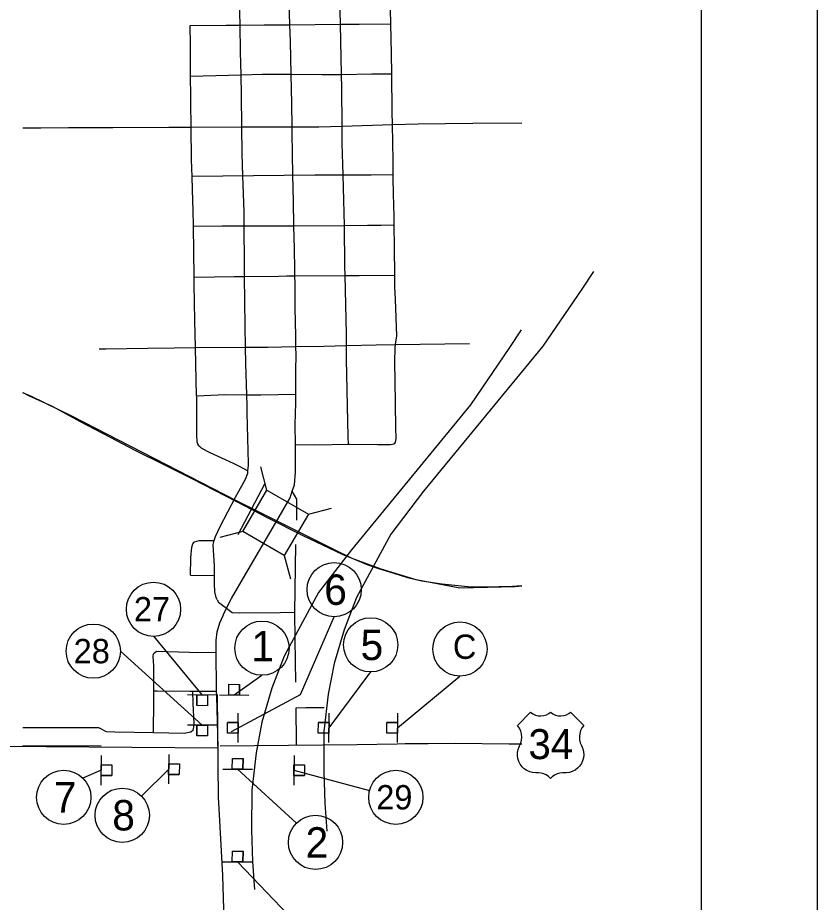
# Model space of a CAD drawing. Extents: x 10133 to 81668, y 5524 to 11018.
# Drawn here: x 16268 to 16868, y 8607 to 9270 of the extents above; entities that cross this region are included whole.
import ezdxf

# ---------------------------------------------------------------- set-up
doc = ezdxf.new("R2010")
doc.units = 0
for name, color, linetype in [('Default', 7, 'Continuous'), ('DisBoundDim', 7, 'Continuous'), ('DisCLMLOR', 7, 'Continuous'), ('DisCLMLSUR', 7, 'Continuous'), ('dsnShtPlotShapeBatchPrint', 7, 'Continuous'), ('Level 3', 7, 'Continuous'), ('trf_Signal_(Temp)_Layout', 7, 'Continuous'), ('trf_SignNumber_Text', 7, 'Continuous')]:
    doc.layers.add(name, color=color, linetype=linetype)

msp = doc.modelspace()

# ---------------------------------------------------------------- linework, layer by layer
at = {"layer": 'Default'}
for p, q in [((16454.98, 8916.03), (16450.39, 8933.39)), ((16433.27, 8882.64), (16453.27, 8920.74)), ((16486.01, 8897.96), (16503.37, 8902.55)), ((16436.91, 8884.99), (16419.55, 8880.41)), ((16467.95, 8866.93), (16472.53, 8849.57))]:
    msp.add_line(p, q, dxfattribs=at)
for points in [[(16434.84, 9264.84), (16434.67, 9274.29), (16433.96, 9308.38), (16433.89, 9316.19)], [(16510.01, 9265.38), (16509.79, 9275.33), (16509.65, 9309.42), (16509.32, 9316.37)], [(16547.84, 9265.77), (16547.84, 9265.77), (16547.29, 9287.29), (16546.86, 9304), (16546.66, 9316.69)], [(16418.34, 8723.02), (16417.4, 8761.37), (16417.24, 8765.29), (16417.16, 8771.93), (16416.96, 8789.48), (16416.96, 8794.43), (16416.96, 8803.2), (16417.67, 8809.71), (16419.65, 8816.36), (16422.05, 8822.05), (16422.33, 8822.73), (16424.76, 8827.47), (16428.42, 8834.61), (16439.17, 8853.28), (16461.38, 8891.34), (16472.41, 8910.29), (16473.97, 8915.18), (16475.53, 8920.06), (16476.38, 8929.39), (16476.29, 8950.19), (16476.23, 8965.33), (16476.52, 8981.31), (16476.57, 8988.1), (16476.71, 9006.22), (16476.8, 9016.96), (16476.58, 9023.71), (16476.5, 9031.84), (16476.09, 9052.47), (16476.09, 9071), (16475.97, 9076.7), (16475.87, 9081.59), (16475.56, 9096.87), (16475.2, 9114.2), (16474.82, 9132.4), (16474.49, 9152.29), (16473.97, 9184.18), (16473.88, 9188.52), (16473.52, 9205.7), (16473.06, 9227.89), (16472.56, 9252.37), (16472.21, 9265.05), (16471, 9308.81)], [(16397.53, 9264.43), (16424.35, 9264.8), (16434.84, 9264.84)], [(16397.77, 9226.48), (16397.71, 9244.04), (16397.69, 9250.03), (16397.53, 9264.43)], [(16434.84, 9264.84), (16452.96, 9264.91), (16459.44, 9264.94), (16472.18, 9265.05), (16510.01, 9265.38)], [(16435.53, 9227.56), (16435.21, 9244.76), (16434.84, 9264.84)], [(16510.01, 9265.38), (16524.09, 9265.5), (16547.84, 9265.77)], [(16510.83, 9227.86), (16510.01, 9265.38)], [(16548.56, 9228.21), (16548.41, 9243.59), (16547.84, 9265.77)], [(16397.77, 9226.48), (16435.53, 9227.56)], [(16399.85, 9113.98), (16399.85, 9113.98), (16399.67, 9126.1), (16399.45, 9132.64), (16398.83, 9151), (16398.83, 9151), (16398.39, 9164.02), (16398.1, 9188.23), (16397.88, 9206.75), (16397.83, 9211.41), (16397.77, 9226.48)], [(16435.53, 9227.56), (16451.51, 9228.01), (16473.04, 9227.89), (16496.12, 9227.76), (16500.46, 9227.73), (16510.83, 9227.86)], [(16437.86, 9114.22), (16437.78, 9124.76), (16437.56, 9131.59), (16436.9, 9151.86), (16436.37, 9168.19), (16436.11, 9188.37), (16435.8, 9212.33), (16435.53, 9227.56)], [(16510.83, 9227.86), (16533.57, 9228.16), (16548.56, 9228.21)], [(16512.12, 9152.47), (16511.48, 9175.88), (16511.35, 9189.08), (16511.06, 9217.47), (16510.83, 9227.86)], [(16549.69, 9152.66), (16549.54, 9163.24), (16549.02, 9190.16), (16548.84, 9199.45), (16548.56, 9228.21)], [(16271.9, 9187.81), (16285.4, 9187.84), (16306.1, 9187.88), (16309.31, 9187.89), (16325.09, 9187.95), (16339.51, 9188), (16381.5, 9188.16), (16398.1, 9188.23), (16436.11, 9188.37), (16473.86, 9188.51), (16493.97, 9188.59), (16511.35, 9189.08), (16549.02, 9190.16), (16568.24, 9190.71), (16609.38, 9191.12), (16646.09, 9191.48)], [(16399.03, 9151.43), (16490.98, 9152.47), (16512.12, 9152.47)], [(16512.12, 9152.47), (16533.14, 9152.47), (16549.69, 9152.66)], [(16513.03, 9114.48), (16512.9, 9124.1), (16512.12, 9152.47)], [(16550.33, 9114.9), (16550.25, 9118.67), (16549.97, 9132.4), (16549.92, 9135.59), (16549.69, 9152.66)], [(16399.85, 9113.98), (16421.38, 9114.27), (16437.86, 9114.22)], [(16400.43, 9075.72), (16399.85, 9113.98)], [(16437.86, 9114.22), (16455.17, 9114.17), (16467.22, 9114.13), (16475.17, 9114.19), (16513.03, 9114.48)], [(16438.18, 9076.3), (16438.07, 9085.57), (16437.86, 9114.22)], [(16513.03, 9114.48), (16530.33, 9114.62), (16540.64, 9114.7), (16550.33, 9114.9)], [(16513.61, 9076.98), (16513.47, 9083.64), (16513.03, 9114.48)], [(16550.88, 9077.26), (16550.68, 9098.02), (16550.33, 9114.9)], [(16400.43, 9075.72), (16430.43, 9076.22), (16438.18, 9076.3)], [(16438.18, 9076.3), (16463.66, 9076.58), (16469.9, 9076.64), (16475.95, 9076.69), (16476.01, 9076.69), (16513.61, 9076.98)], [(16438.95, 9023.22), (16438.63, 9039.31), (16438.18, 9076.3)], [(16699.75, 9080.1), (16690.96, 9066.76), (16661.71, 9023.97), (16572.44, 8915.18), (16547.74, 8883.05), (16522.03, 8835.36), (16512.85, 8811.29), (16505.34, 8785.98), (16500.94, 8762.86), (16497.64, 8734.98), (16497.55, 8705.05), (16498.28, 8681.21), (16499.87, 8660.29)], [(16513.61, 9076.98), (16524.09, 9077.07), (16550.88, 9077.26)], [(16516.11, 8950.45), (16515.73, 8955.89), (16514.6, 9014.32), (16514.6, 9024.42), (16514.6, 9033.13), (16513.61, 9076.98)], [(16516.11, 8950.45), (16516.86, 8950.47), (16537.8, 8950.19), (16547.71, 8950.19), (16550.11, 8950.61), (16550.11, 8950.61), (16550.76, 8951.34), (16551.24, 8951.88), (16551.81, 8954.57), (16551.67, 8962.92), (16551.05, 8998.18), (16550.82, 9011.87), (16551.1, 9023.04), (16551.37, 9025.11), (16552.23, 9031.67), (16551.29, 9059.06), (16550.96, 9068.6), (16550.88, 9077.26)], [(16401.35, 9022.91), (16400.94, 9043.2), (16400.51, 9070.22), (16400.43, 9075.72)], [(16645.64, 9036.2), (16636.85, 9022.87), (16607.59, 8980.08), (16518.32, 8871.29), (16493.62, 8839.16), (16467.91, 8791.47), (16458.74, 8767.39), (16451.22, 8742.08), (16446.82, 8718.97), (16443.52, 8691.09), (16443.43, 8661.16), (16444.16, 8637.31), (16445.75, 8616.39)], [(16438.95, 9023.22), (16455.53, 9023.35), (16476.55, 9023.7), (16476.64, 9023.71)], [(16476.64, 9023.71), (16497.69, 9024.06), (16514.6, 9024.42), (16536.88, 9024.91), (16551.37, 9025.11), (16606.9, 9025.9)], [(16329.24, 9021.94), (16334.15, 9021.94), (16365.52, 9022.46)], [(16365.52, 9022.46), (16385.5, 9022.79), (16401.35, 9022.91)], [(16401.35, 9022.91), (16438.95, 9023.22)], [(16402.08, 8986.85), (16401.35, 9022.91)], [(16439.83, 8987.59), (16439.2, 9010.88), (16438.95, 9023.22)], [(16271.9, 8989.2), (16276.34, 8987.08), (16294.06, 8978.91), (16314.96, 8967.45), (16337.03, 8955.99), (16356.55, 8945.7), (16377.23, 8935.41), (16399.19, 8924.49), (16432.19, 8907.51), (16444.12, 8901.25), (16455.63, 8895.21), (16481.94, 8881.94), (16511.43, 8867.94), (16518.1, 8865.2), (16530.53, 8860.09), (16538.48, 8857.33), (16550.05, 8853.62), (16560.23, 8850.54), (16571.16, 8848.1), (16586.12, 8845.66), (16598.42, 8844.39), (16605.53, 8843.75), (16619.11, 8843.54), (16639.16, 8843.86), (16646.09, 8844.52)], [(16646.09, 8844.1), (16641.1, 8843.45), (16599.55, 8842.54), (16566.9, 8848.72), (16540.5, 8856.8), (16518.78, 8864.85), (16505.54, 8871.22), (16432.18, 8907.92), (16308.7, 8971.47), (16278.49, 8986.15), (16271.9, 8988.93)], [(16402.08, 8986.85), (16402.21, 8980.39), (16402.07, 8957.75), (16402.49, 8952.24), (16403.49, 8949.83), (16404.72, 8948.73), (16406.03, 8947.57), (16412.26, 8944.32), (16429.57, 8936.16), (16434.18, 8933.99), (16440.75, 8930.55)], [(16402.08, 8986.85), (16424.01, 8987.67), (16439.83, 8987.59)], [(16439.83, 8987.59), (16450.32, 8987.53), (16463.44, 8987.81), (16476.55, 8988.1)], [(16440.75, 8930.55), (16441.09, 8934.8), (16441.18, 8935.9), (16440.19, 8973.88), (16440.05, 8979.33), (16439.83, 8987.59)], [(16476.27, 8950.18), (16490.78, 8949.9), (16516.11, 8950.45)], [(16415.51, 8878.27), (16416.28, 8881.15), (16419.96, 8888.65), (16431.42, 8910.72), (16438.92, 8924.16), (16440.61, 8928.82), (16440.75, 8930.55)], [(16477.36, 8893.55), (16477.36, 8893.97), (16477.42, 8902.56), (16477.31, 8909.2), (16473.95, 8915.17)], [(16397.6, 8852.2), (16398.03, 8865.16), (16398.74, 8873.23), (16399.45, 8875.63), (16399.45, 8875.63), (16400.4, 8876.91), (16400.72, 8877.33), (16404.26, 8878.18), (16408.92, 8878.32), (16415.51, 8878.27)], [(16415.64, 8852.05), (16415.71, 8859.08), (16414.72, 8875.35), (16415.51, 8878.27)], [(16475.94, 8824.37), (16476.59, 8875.27)], [(16397.6, 8852.2), (16415.64, 8852.05)], [(16417.74, 8833.8), (16416.85, 8835.45), (16415.86, 8839.7), (16415.57, 8845.92), (16415.64, 8852.05)], [(16417.74, 8833.8), (16418.69, 8832.06), (16421.66, 8829.8), (16424.75, 8827.48), (16429.01, 8824.28), (16434.53, 8824), (16464.8, 8824.28), (16475.94, 8824.37)], [(16476.64, 8771.9), (16476.21, 8804.01), (16475.94, 8824.37)], [(16370.16, 8765.56), (16370.16, 8784.24), (16369.74, 8791.32), (16369.88, 8793.3), (16370.59, 8794), (16370.7, 8794.09), (16372.23, 8795.28), (16396.9, 8794.37), (16402.93, 8794.14), (16416.94, 8794.43)], [(16369.92, 8734.18), (16370.16, 8758.07), (16370.16, 8765.56)], [(16369.92, 8734.18), (16392.8, 8733.74), (16398.03, 8734.73), (16399.58, 8736.27), (16400.01, 8736.71), (16400.29, 8740.67), (16399.73, 8756.23), (16399.36, 8765.28)], [(16370.16, 8765.56), (16372.66, 8765.57), (16397.13, 8765.28), (16399.36, 8765.28)], [(16399.36, 8765.28), (16417.22, 8765.28)], [(16476.89, 8752.69), (16484.04, 8752.98), (16497.77, 8752.98)], [(16477.11, 8724.98), (16477.08, 8726.46), (16476.89, 8752.69)], [(16271.9, 8737.89), (16328.66, 8737.89), (16334.37, 8734.87), (16340.88, 8734.73), (16369.92, 8734.18)], [(16224.74, 8724.16), (16418.19, 8722.71)], [(16271.9, 8724.49), (16330.68, 8724.13)]]:
    msp.add_lwpolyline(points, dxfattribs=at)
for points in [[(16436.91, 8884.99), (16454.98, 8916.03), (16486.01, 8897.96), (16467.95, 8866.93)], [(16642.71, 8739.57), (16652.57, 8749.43), (16654.3, 8748.21), (16656.22, 8747.33), (16658.27, 8746.81), (16660.37, 8746.67), (16662.47, 8746.92), (16664.49, 8747.55), (16666.36, 8748.53), (16667.57, 8749.43), (16669.3, 8748.21), (16671.22, 8747.33), (16673.27, 8746.81), (16675.38, 8746.67), (16677.47, 8746.92), (16679.49, 8747.55), (16681.36, 8748.53), (16682.58, 8749.43), (16692.43, 8739.57), (16691.1, 8737.7), (16690.09, 8735.63), (16689.44, 8733.43), (16689.17, 8731.14), (16689.29, 8728.84), (16689.79, 8726.6), (16690.65, 8724.47), (16691.71, 8722.09), (16692.26, 8719.85), (16692.42, 8717.56), (16692.21, 8715.27), (16691.61, 8713.05), (16690.65, 8710.96), (16689.35, 8709.06), (16687.75, 8707.4), (16685.9, 8706.03), (16683.85, 8705), (16681.66, 8704.32), (16679.38, 8704.01), (16678.24, 8704), (16676.57, 8704), (16674.46, 8703.8), (16672.43, 8703.23), (16670.53, 8702.3), (16668.84, 8701.04), (16667.57, 8699.71), (16666.1, 8701.22), (16664.38, 8702.44), (16662.46, 8703.33), (16660.41, 8703.85), (16658.58, 8704), (16656.44, 8704), (16654.15, 8704.19), (16651.92, 8704.76), (16649.82, 8705.7), (16647.91, 8706.97), (16646.23, 8708.55), (16644.84, 8710.38), (16643.78, 8712.43), (16643.08, 8714.61), (16642.75, 8716.89), (16642.8, 8719.19), (16643.24, 8721.45), (16644.05, 8723.6), (16644.35, 8724.2), (16645.27, 8726.31), (16645.82, 8728.54), (16645.98, 8730.83), (16645.77, 8733.12), (16645.17, 8735.35), (16644.21, 8737.44)]]:
    msp.add_lwpolyline(points, close=True, dxfattribs=at)
at = {"layer": 'DisBoundDim'}
for p, q in [((16426.4, 8762.4), (16426.46, 8770.4)), ((16426.46, 8770.4), (16434.46, 8770.35)), ((16434.4, 8762.35), (16434.46, 8770.35)), ((16417.51, 8762.26), (16395.38, 8762.42)), ((16402.45, 8762.37), (16402.39, 8754.37)), ((16410.45, 8762.31), (16410.39, 8754.31)), ((16419.34, 8762.45), (16441.47, 8762.3)), ((16410.39, 8754.31), (16402.39, 8754.37)), ((16433.3, 8726.62), (16433.46, 8748.75)), ((16501.43, 8726.62), (16501.58, 8748.75)), ((16552.82, 8726.62), (16552.97, 8748.75)), ((16417.51, 8739.62), (16395.38, 8739.77)), ((16402.45, 8739.72), (16402.39, 8731.72)), ((16410.45, 8739.67), (16410.39, 8731.67)), ((16425.35, 8733.74), (16425.41, 8741.74)), ((16433.41, 8741.69), (16425.41, 8741.74)), ((16493.48, 8733.74), (16493.54, 8741.74)), ((16501.53, 8741.69), (16493.54, 8741.74)), ((16544.87, 8733.74), (16544.92, 8741.74)), ((16552.92, 8741.69), (16544.92, 8741.74)), ((16410.39, 8731.67), (16402.39, 8731.72)), ((16433.35, 8733.69), (16425.35, 8733.74)), ((16501.48, 8733.69), (16493.48, 8733.74)), ((16552.87, 8733.69), (16544.87, 8733.74)), ((16330.72, 8716.99), (16330.57, 8694.85)), ((16381.38, 8717.79), (16381.23, 8695.66)), ((16428.98, 8706.75), (16429.04, 8714.75)), ((16429.04, 8714.75), (16437.04, 8714.7)), ((16436.98, 8706.7), (16437.04, 8714.7)), ((16475.29, 8716.99), (16475.13, 8694.85)), ((16330.67, 8709.92), (16338.67, 8709.86)), ((16338.67, 8709.86), (16338.61, 8701.86)), ((16381.33, 8710.72), (16389.33, 8710.67)), ((16389.33, 8710.67), (16389.28, 8702.67)), ((16421.92, 8706.8), (16444.05, 8706.65)), ((16475.24, 8709.92), (16483.24, 8709.86)), ((16483.24, 8709.86), (16483.18, 8701.86)), ((16330.61, 8701.92), (16338.61, 8701.86)), ((16381.28, 8702.72), (16389.28, 8702.67)), ((16475.18, 8701.92), (16483.18, 8701.86)), ((16428.98, 8637.26), (16429.04, 8645.26)), ((16429.04, 8645.26), (16437.04, 8645.21)), ((16436.98, 8637.21), (16437.04, 8645.21)), ((16421.92, 8637.31), (16444.05, 8637.16))]:
    msp.add_line(p, q, dxfattribs=at)
at = {"layer": 'DisCLMLOR'}
for p, q in [((16426.4, 8762.4), (16426.46, 8770.4)), ((16426.4, 8762.4), (16426.46, 8770.4)), ((16426.4, 8762.4), (16426.46, 8770.4)), ((16426.4, 8762.4), (16426.46, 8770.4)), ((16426.46, 8770.4), (16434.46, 8770.35)), ((16426.46, 8770.4), (16434.46, 8770.35)), ((16426.46, 8770.4), (16434.46, 8770.35)), ((16426.46, 8770.4), (16434.46, 8770.35)), ((16434.46, 8770.35), (16434.4, 8762.35)), ((16434.46, 8770.35), (16434.4, 8762.35)), ((16434.46, 8770.35), (16434.4, 8762.35)), ((16434.46, 8770.35), (16434.4, 8762.35)), ((16402.39, 8754.37), (16402.45, 8762.37)), ((16402.39, 8754.37), (16402.45, 8762.37)), ((16402.39, 8754.37), (16402.45, 8762.37)), ((16402.39, 8754.37), (16402.45, 8762.37)), ((16402.45, 8762.37), (16410.45, 8762.31)), ((16402.45, 8762.37), (16410.45, 8762.31)), ((16402.45, 8762.37), (16410.45, 8762.31)), ((16402.45, 8762.37), (16410.45, 8762.31)), ((16410.45, 8762.31), (16410.39, 8754.31)), ((16410.45, 8762.31), (16410.39, 8754.31)), ((16410.45, 8762.31), (16410.39, 8754.31)), ((16410.45, 8762.31), (16410.39, 8754.31)), ((16434.4, 8762.35), (16426.4, 8762.4)), ((16434.4, 8762.35), (16426.4, 8762.4)), ((16434.4, 8762.35), (16426.4, 8762.4)), ((16434.4, 8762.35), (16426.4, 8762.4)), ((16410.39, 8754.31), (16402.39, 8754.37)), ((16410.39, 8754.31), (16402.39, 8754.37)), ((16410.39, 8754.31), (16402.39, 8754.37)), ((16410.39, 8754.31), (16402.39, 8754.37)), ((16402.39, 8731.72), (16402.45, 8739.72)), ((16402.39, 8731.72), (16402.45, 8739.72)), ((16402.39, 8731.72), (16402.45, 8739.72)), ((16402.39, 8731.72), (16402.45, 8739.72)), ((16402.45, 8739.72), (16410.45, 8739.67)), ((16402.45, 8739.72), (16410.45, 8739.67)), ((16402.45, 8739.72), (16410.45, 8739.67)), ((16402.45, 8739.72), (16410.45, 8739.67)), ((16410.45, 8739.67), (16410.39, 8731.67)), ((16410.45, 8739.67), (16410.39, 8731.67)), ((16410.45, 8739.67), (16410.39, 8731.67)), ((16410.45, 8739.67), (16410.39, 8731.67)), ((16425.35, 8733.74), (16425.41, 8741.74)), ((16425.35, 8733.74), (16425.41, 8741.74)), ((16425.35, 8733.74), (16425.41, 8741.74)), ((16425.35, 8733.74), (16425.41, 8741.74)), ((16425.41, 8741.74), (16433.41, 8741.69)), ((16425.41, 8741.74), (16433.41, 8741.69)), ((16425.41, 8741.74), (16433.41, 8741.69)), ((16425.41, 8741.74), (16433.41, 8741.69)), ((16433.41, 8741.69), (16433.35, 8733.69)), ((16433.41, 8741.69), (16433.35, 8733.69)), ((16433.41, 8741.69), (16433.35, 8733.69)), ((16433.41, 8741.69), (16433.35, 8733.69)), ((16493.48, 8733.74), (16493.54, 8741.74)), ((16493.48, 8733.74), (16493.54, 8741.74)), ((16493.48, 8733.74), (16493.54, 8741.74)), ((16493.48, 8733.74), (16493.54, 8741.74)), ((16493.54, 8741.74), (16501.53, 8741.69)), ((16493.54, 8741.74), (16501.53, 8741.69)), ((16493.54, 8741.74), (16501.53, 8741.69)), ((16493.54, 8741.74), (16501.53, 8741.69)), ((16501.53, 8741.69), (16501.48, 8733.69)), ((16501.53, 8741.69), (16501.48, 8733.69)), ((16501.53, 8741.69), (16501.48, 8733.69)), ((16501.53, 8741.69), (16501.48, 8733.69)), ((16544.87, 8733.74), (16544.92, 8741.74)), ((16544.87, 8733.74), (16544.92, 8741.74)), ((16544.87, 8733.74), (16544.92, 8741.74)), ((16544.87, 8733.74), (16544.92, 8741.74)), ((16544.92, 8741.74), (16552.92, 8741.69)), ((16544.92, 8741.74), (16552.92, 8741.69)), ((16544.92, 8741.74), (16552.92, 8741.69)), ((16544.92, 8741.74), (16552.92, 8741.69)), ((16552.92, 8741.69), (16552.87, 8733.69)), ((16552.92, 8741.69), (16552.87, 8733.69)), ((16552.92, 8741.69), (16552.87, 8733.69)), ((16552.92, 8741.69), (16552.87, 8733.69)), ((16410.39, 8731.67), (16402.39, 8731.72)), ((16410.39, 8731.67), (16402.39, 8731.72)), ((16410.39, 8731.67), (16402.39, 8731.72)), ((16410.39, 8731.67), (16402.39, 8731.72)), ((16433.35, 8733.69), (16425.35, 8733.74)), ((16433.35, 8733.69), (16425.35, 8733.74)), ((16433.35, 8733.69), (16425.35, 8733.74)), ((16433.35, 8733.69), (16425.35, 8733.74)), ((16501.48, 8733.69), (16493.48, 8733.74)), ((16501.48, 8733.69), (16493.48, 8733.74)), ((16501.48, 8733.69), (16493.48, 8733.74)), ((16501.48, 8733.69), (16493.48, 8733.74)), ((16552.87, 8733.69), (16544.87, 8733.74)), ((16552.87, 8733.69), (16544.87, 8733.74)), ((16552.87, 8733.69), (16544.87, 8733.74)), ((16552.87, 8733.69), (16544.87, 8733.74)), ((16428.98, 8706.75), (16429.04, 8714.75)), ((16428.98, 8706.75), (16429.04, 8714.75)), ((16428.98, 8706.75), (16429.04, 8714.75)), ((16428.98, 8706.75), (16429.04, 8714.75)), ((16429.04, 8714.75), (16437.04, 8714.7)), ((16429.04, 8714.75), (16437.04, 8714.7)), ((16429.04, 8714.75), (16437.04, 8714.7)), ((16429.04, 8714.75), (16437.04, 8714.7)), ((16437.04, 8714.7), (16436.98, 8706.7)), ((16437.04, 8714.7), (16436.98, 8706.7)), ((16437.04, 8714.7), (16436.98, 8706.7)), ((16437.04, 8714.7), (16436.98, 8706.7)), ((16330.61, 8701.92), (16330.67, 8709.92)), ((16330.61, 8701.92), (16330.67, 8709.92)), ((16330.61, 8701.92), (16330.67, 8709.92)), ((16330.61, 8701.92), (16330.67, 8709.92)), ((16330.67, 8709.92), (16338.67, 8709.86)), ((16330.67, 8709.92), (16338.67, 8709.86)), ((16330.67, 8709.92), (16338.67, 8709.86)), ((16330.67, 8709.92), (16338.67, 8709.86)), ((16338.67, 8709.86), (16338.61, 8701.86)), ((16338.67, 8709.86), (16338.61, 8701.86)), ((16338.67, 8709.86), (16338.61, 8701.86)), ((16338.67, 8709.86), (16338.61, 8701.86)), ((16381.28, 8702.72), (16381.33, 8710.72)), ((16381.28, 8702.72), (16381.33, 8710.72)), ((16381.28, 8702.72), (16381.33, 8710.72)), ((16381.28, 8702.72), (16381.33, 8710.72)), ((16381.33, 8710.72), (16389.33, 8710.67)), ((16381.33, 8710.72), (16389.33, 8710.67)), ((16381.33, 8710.72), (16389.33, 8710.67)), ((16381.33, 8710.72), (16389.33, 8710.67)), ((16389.33, 8710.67), (16389.28, 8702.67)), ((16389.33, 8710.67), (16389.28, 8702.67)), ((16389.33, 8710.67), (16389.28, 8702.67)), ((16389.33, 8710.67), (16389.28, 8702.67)), ((16436.98, 8706.7), (16428.98, 8706.75)), ((16436.98, 8706.7), (16428.98, 8706.75)), ((16436.98, 8706.7), (16428.98, 8706.75)), ((16436.98, 8706.7), (16428.98, 8706.75)), ((16475.18, 8701.92), (16475.24, 8709.92)), ((16475.18, 8701.92), (16475.24, 8709.92)), ((16475.18, 8701.92), (16475.24, 8709.92)), ((16475.18, 8701.92), (16475.24, 8709.92)), ((16475.24, 8709.92), (16483.24, 8709.86)), ((16475.24, 8709.92), (16483.24, 8709.86)), ((16475.24, 8709.92), (16483.24, 8709.86)), ((16475.24, 8709.92), (16483.24, 8709.86)), ((16483.24, 8709.86), (16483.18, 8701.86)), ((16483.24, 8709.86), (16483.18, 8701.86)), ((16483.24, 8709.86), (16483.18, 8701.86)), ((16483.24, 8709.86), (16483.18, 8701.86)), ((16338.61, 8701.86), (16330.61, 8701.92)), ((16338.61, 8701.86), (16330.61, 8701.92)), ((16338.61, 8701.86), (16330.61, 8701.92)), ((16338.61, 8701.86), (16330.61, 8701.92)), ((16389.28, 8702.67), (16381.28, 8702.72)), ((16389.28, 8702.67), (16381.28, 8702.72)), ((16389.28, 8702.67), (16381.28, 8702.72)), ((16389.28, 8702.67), (16381.28, 8702.72)), ((16483.18, 8701.86), (16475.18, 8701.92)), ((16483.18, 8701.86), (16475.18, 8701.92)), ((16483.18, 8701.86), (16475.18, 8701.92)), ((16483.18, 8701.86), (16475.18, 8701.92)), ((16428.98, 8637.26), (16429.04, 8645.26)), ((16428.98, 8637.26), (16429.04, 8645.26)), ((16428.98, 8637.26), (16429.04, 8645.26)), ((16428.98, 8637.26), (16429.04, 8645.26)), ((16429.04, 8645.26), (16437.04, 8645.21)), ((16429.04, 8645.26), (16437.04, 8645.21)), ((16429.04, 8645.26), (16437.04, 8645.21)), ((16429.04, 8645.26), (16437.04, 8645.21)), ((16437.04, 8645.21), (16436.98, 8637.21)), ((16437.04, 8645.21), (16436.98, 8637.21)), ((16437.04, 8645.21), (16436.98, 8637.21)), ((16437.04, 8645.21), (16436.98, 8637.21)), ((16436.98, 8637.21), (16428.98, 8637.26)), ((16436.98, 8637.21), (16428.98, 8637.26)), ((16436.98, 8637.21), (16428.98, 8637.26)), ((16436.98, 8637.21), (16428.98, 8637.26))]:
    msp.add_line(p, q, dxfattribs=at)
at = {"layer": 'DisCLMLSUR'}
for p, q in [((16480.08, 8762.8), (16505.36, 8821.03)), ((16369.92, 8806.36), (16406.45, 8762.34)), ((16345.1, 8795.25), (16406.45, 8739.69)), ((16501.51, 8737.69), (16532.78, 8779.64)), ((16430.4, 8762.37), (16451.24, 8777.14)), ((16552.9, 8737.69), (16599.65, 8776.45)), ((16428.33, 8734.87), (16480.08, 8762.8)), ((16330.64, 8705.92), (16317.03, 8699.97)), ((16381.31, 8706.72), (16360.86, 8686.55)), ((16432.98, 8706.72), (16477.01, 8666.15)), ((16475.21, 8705.92), (16531.93, 8690.84)), ((16432.98, 8637.23), (16477.01, 8591.2))]:
    msp.add_line(p, q, dxfattribs=at)
at = {"layer": 'dsnShtPlotShapeBatchPrint'}
msp.add_lwpolyline([(16424.33, 8544.34), (16421.91, 8626.65), (16421.89, 8626.93), (16419.85, 8663.58), (16418.85, 8681.67), (16418.66, 8685.08), (16417.89, 8762.73)], dxfattribs=at)
at = {"layer": 'Level 3'}
msp.add_lwpolyline([(13732.52, 9944.02), (16867.53, 9944.02), (16867.53, 7924.02), (13732.52, 7924.02)], close=True, dxfattribs=at)
at = {"layer": 'trf_Signal_(Temp)_Layout'}
msp.add_lwpolyline([(16151.16, 9682.4), (16780.52, 9682.4), (16780.52, 8361.35), (16151.16, 8361.35)], close=True, dxfattribs=at)
msp.add_lwpolyline([(16419.92, 8724.21), (16522.45, 8725.31), (16552.52, 8725.82), (16558.61, 8725.88), (16575.73, 8726.05), (16596.38, 8726.25), (16636.55, 8725.82), (16646.09, 8725.64)], dxfattribs=at)
at = {"layer": 'trf_SignNumber_Text'}
for centre in [(16505.36, 8841.36), (16369.92, 8826.68), (16451.24, 8797.47), (16532.78, 8799.97), (16324.77, 8795.25), (16599.65, 8796.78), (16302.66, 8685.6), (16551.57, 8685.62), (16346.48, 8672.18), (16491.38, 8651.78)]:
    msp.add_circle(centre, 20.33, dxfattribs=at)

# ---------------------------------------------------------------- texts
at = {"layer": 'Default'}
msp.add_text('34', height=22.5, dxfattribs=at).set_placement((16651.01, 8714.27))
at = {"layer": 'trf_SignNumber_Text'}
for s, height, p in [('6', 22.82, (16497.9, 8829.95)), ('27', 18.258, (16355.22, 8817.59)), ('5', 22.82, (16525.14, 8788.55)), ('28', 18.258, (16310.06, 8786.16)), ('1', 22.82, (16443.27, 8787.54)), ('C', 18.26, (16594.34, 8789.45)), ('7', 22.82, (16295.2, 8674.19)), ('29', 18.258, (16536.87, 8676.52)), ('8', 22.82, (16339.02, 8660.77)), ('2', 22.82, (16483.93, 8640.37))]:
    msp.add_text(s, height=height, dxfattribs=at).set_placement(p)

doc.saveas('drawing.dxf')
